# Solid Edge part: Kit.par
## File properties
Dokumentum tartalom típus: 0
Last saved by: bmolnar
Revision: 77
Sűrűség: 0,000 kg/m^3
Pontosság: 0,990
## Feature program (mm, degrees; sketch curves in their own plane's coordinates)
base feature "unnamed BaseFeature 1"
sketch for "unnamed Hole 1" plane through (-0.0012, 0, 85.35) normal (0, 0, -1) x-axis (-1, 0, 0)
  hole centre (-0.0012, 0) bore radius 8
hole "unnamed Hole 1" through
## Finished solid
Body 1: solid body, 46 faces, 63 edges, 49 vertices, 1 internal void.
  Faces by surface: cylinder 16, cone 14, plane 12, torus 4
  Edges by curve: circle 49, line 14
Bounding box of the edges (mm; curved faces can reach further): 68.000 x 67.800 x 14.500, from (-34, -32.35, 85.35) to (34, 35.45, 99.85).
Cylindrical faces by radius (mm): R1.5 x2, R3 x4, R8 x1, R8.27 x1, R8.85 x1, R9 x1, R10.16 x1, R10.25 x1, R19.25 x1, R29.65 x1, R32.35 x1, R34 x1
Conical faces (half-angle, radius in mm at the cone's reference point): 3 deg R10.205 x1, 7 deg R9.5925 x1, 14 deg R8.135 x1, 14 deg R8.4811 x1, 17 deg R8.135 x1, 23 deg R8.829 x1, 42.5 deg R8.1233 x1, 45 deg R9.1 x2, 45 deg R18.75 x1, 84 deg R76.3675 x2, 85 deg R9.9463 x1, 87 deg R8.1765 x1
Toroidal faces (ring radius, tube radius in mm): R8.8057 r0.2025 x1, R9.2522 r0.2925 x1, R9.96 r0.2 x1, R20.05 r0.8 x1
Planar faces by outward normal: +z 7, -z 3, oblique 2
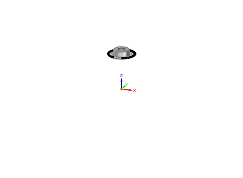
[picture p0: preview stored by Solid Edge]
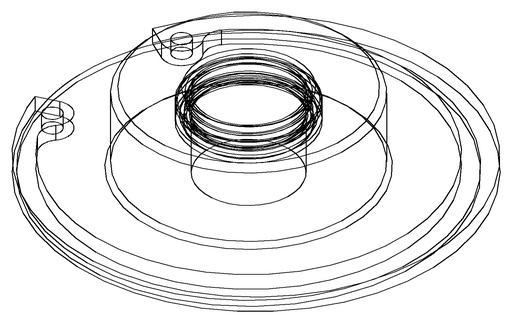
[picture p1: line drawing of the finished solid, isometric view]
